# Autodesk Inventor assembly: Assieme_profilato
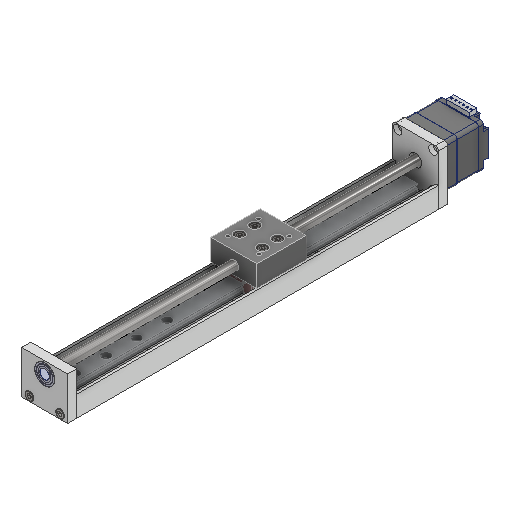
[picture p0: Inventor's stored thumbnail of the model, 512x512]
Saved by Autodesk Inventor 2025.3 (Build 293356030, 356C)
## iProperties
Created: 2025-11
Part Number: Assieme_profilato
Document SubType Name: Assembly
Designer: R5800u
Author: R5800u
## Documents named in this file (11)
- C:\Users\R5800u\Desktop\Nuova cartella (2)\Actuator\Actuator_movable\Actuator_movable\Assieme_profilato.iam
- C:\Users\R5800u\Desktop\Nuova cartella (2)\Actuator\Actuator_movable\Actuator_movable\profilato.ipt
- C:\Users\R5800u\Desktop\Nuova cartella (2)\Actuator\Actuator_movable\Actuator_movable\profilato_cuscinetto.ipt
- C:\Users\R5800u\Desktop\Nuova cartella (2)\Actuator\Actuator_movable\Actuator_movable\profilato_motore.ipt
- C:\Users\R5800u\Desktop\Nuova cartella (2)\Actuator\Actuator_movable\Actuator_movable\Nema11.ipt
- C:\Users\R5800u\Desktop\Nuova cartella (2)\Actuator\Actuator_movable\Actuator_movable\00144585.iam
- C:\Users\R5800u\Desktop\Nuova cartella (2)\Actuator\Actuator_movable\Actuator_movable\Actuator_MGN9.ipt
- C:\Users\R5800u\Documents\Inventor\Content Center Files\R2025\it-IT\AS 1420\AS 1420 - 1973 - M3 x 6.ipt
- C:\Users\R5800u\Desktop\Nuova cartella (2)\Actuator\Actuator_movable\Actuator_movable\Actuator_MGN9C.ipt
- C:\Users\R5800u\Desktop\Nuova cartella (2)\Actuator\Actuator_movable\Actuator_movable\Carriage.ipt
- C:\Users\R5800u\Documents\Inventor\Content Center Files\R2025\it-IT\AS 1420\AS 1420 - 1973 - M3 x 12.ipt
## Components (16 placed, 10 different names)
1. profilato:1
2. profilato_cuscinetto:1
3. profilato_motore:1
4. Nema11:1 — Coincidente:8, Coincidente:9, Coincidente:10, Coincidente:16
5. 00144585:1 [sub-assembly] — Rotazionale:1
6. Actuator_MGN9:1 — Coincidente:11, Coincidente:12, Coincidente:13, Coincidente:14, Coincidente:15
7. AS 1420 - Metrico M3 x 6:1
8. AS 1420 - Metrico M3 x 6:2
9. AS 1420 - Metrico M3 x 6:3
10. AS 1420 - Metrico M3 x 6:4
11. Actuator_MGN9C:1 — Coincidente:14, Coincidente:15, Coincidente:17, Coincidente:18
12. Carriage:1
13. AS 1420 - Metrico M3 x 12:1
14. AS 1420 - Metrico M3 x 12:2
15. AS 1420 - Metrico M3 x 12:3
16. AS 1420 - Metrico M3 x 12:4
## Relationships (12: Mate 11, RevoluteJoint 1)
- Coincidente:8 [Mate]: Nema11:1
- Coincidente:9 [Mate]: Nema11:1
- Coincidente:10 [Mate]: Nema11:1
- Rotazionale:1 [RevoluteJoint]: 00144585:1
- Coincidente:11 [Mate]: Actuator_MGN9:1
- Coincidente:12 [Mate]: Actuator_MGN9:1
- Coincidente:13 [Mate]: Actuator_MGN9:1
- Coincidente:14 [Mate]: Actuator_MGN9:1 ↔ Actuator_MGN9C:1
- Coincidente:15 [Mate]: Actuator_MGN9:1 ↔ Actuator_MGN9C:1
- Coincidente:16 [Mate]: Nema11:1
- Coincidente:17 [Mate]: Actuator_MGN9C:1
- Coincidente:18 [Mate]: Actuator_MGN9C:1
